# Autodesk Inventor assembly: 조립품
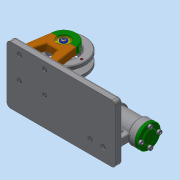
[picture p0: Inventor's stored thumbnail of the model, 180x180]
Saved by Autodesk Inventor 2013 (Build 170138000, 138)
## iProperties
Created: 2018-01
Part Number: 조립품
Document SubType Name: Assembly
Designer: dgall
Author: dgall
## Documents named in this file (19)
- C:\Users\dgall\Desktop\380107V1016\조립품.iam
- C:\Users\dgall\Desktop\380107V1016\플레이트.ipt
- C:\Users\dgall\Desktop\380107V1016\지지대-A.ipt
- C:\Users\dgall\Desktop\380107V1016\베어링커버-A.ipt
- C:\Users\dgall\Desktop\380107V1016\베어링 8x22x7.ipt
- C:\Users\dgall\Desktop\380107V1016\스페이서.ipt
- C:\Users\dgall\Desktop\380107V1016\V-벨트풀리.ipt
- C:\Users\dgall\Desktop\380107V1016\크랭크축.ipt
- C:\Users\dgall\Desktop\380107V1016\하우징.ipt
- C:\Users\dgall\Desktop\380107V1016\하우징커버-A.ipt
- C:\Users\dgall\Desktop\380107V1016\하우징커버-B.ipt
- C:\Users\dgall\Desktop\380107V1016\플랜지.ipt
- C:\Users\dgall\Desktop\380107V1016\커넥팅로드-A.ipt
- C:\Users\dgall\Desktop\380107V1016\커넥팅로드-B.ipt
- C:\Users\dgall\Desktop\380107V1016\피스톤.ipt
- C:\Users\dgall\Desktop\380107V1016\3mm 와셔.ipt
- C:\Users\dgall\Desktop\380107V1016\볼트 M3x8.ipt
- C:\Users\dgall\Desktop\380107V1016\볼트 M3x12.ipt
- C:\Users\dgall\Desktop\380107V1016\둥근머리볼트 M3x12.ipt
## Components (9 placed, 8 different names)
1. 플레이트:1
2. V-벨트풀리:1
3. 하우징:1
4. 하우징커버-A:1
5. 하우징커버-B:1
6. 플랜지:1
7. 피스톤:1
8. 3mm 와셔:1
9. 3mm 와셔:2
